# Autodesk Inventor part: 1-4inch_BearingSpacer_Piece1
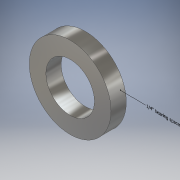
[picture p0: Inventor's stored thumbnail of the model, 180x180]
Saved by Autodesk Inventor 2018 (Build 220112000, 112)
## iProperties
Created: 2018-01
Part Number: 1-4inch_BearingSpacer_Piece1
Material: Generic
Document SubType Name: Modeling
Designer: Olivier
Density: 1 g/cm^3
Appearance: Default
Author: Olivier
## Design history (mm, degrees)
node "Annotations"
  node "Leader Text 1"
sketch "Sketch1" dims "d2" = 2.8956 (derived), "d3" = 0.46723 (derived)
  geometry: C1 r 10.1 at (0, 0); C2 r 17 at (0, 0); C3 r 17 at (0, 0); C4 r 10.1 at (0, 0); 1 further point
  constraints: 4 centre point
extrude "Extrusion1" new body sketch "Sketch1" distance "d0" = 6.35; taper "d1" = 0 deg
body "Solid1"
